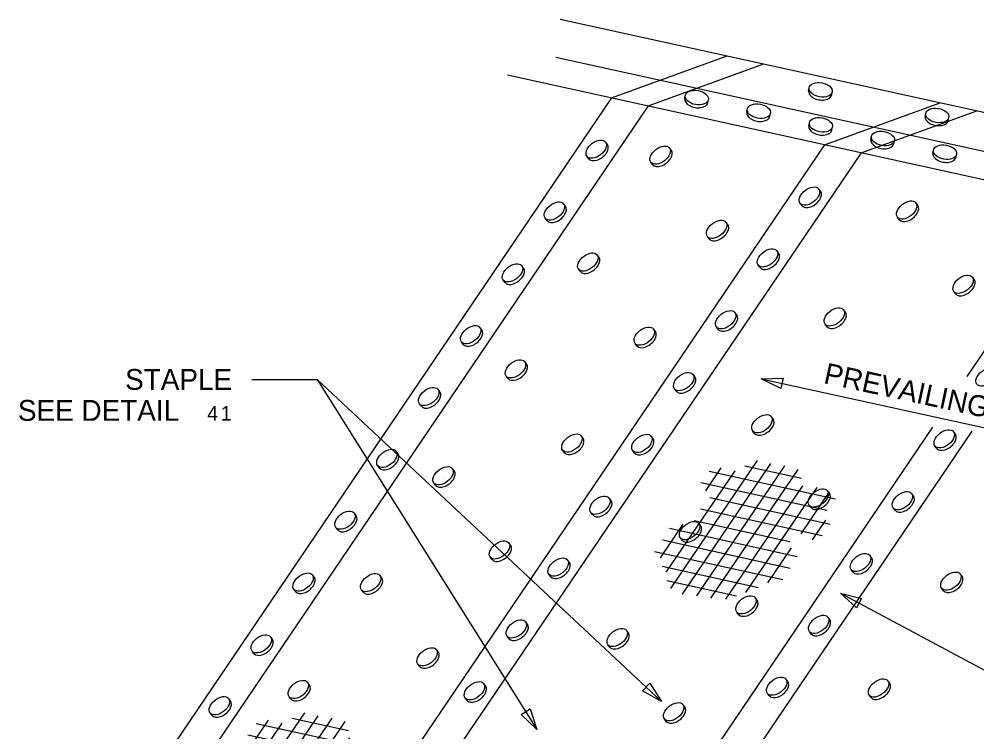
# Model space of a CAD drawing. Extents: x 27123946 to 27124151, y 1145898 to 1146027.
# Drawn here: x 27123951.53 to 27123989.43, y 1145983.24 to 1146011.45 of the extents above; entities that cross this region are included whole.
import ezdxf

# ---------------------------------------------------------------- set-up
doc = ezdxf.new("R2010")
doc.units = 0
for name, color, linetype in [('C-EROS', 7, 'Continuous'), ('C-PVMT', 7, 'Continuous'), ('Default', 7, 'Continuous'), ('G-ANNO-TEXT', 7, 'Continuous')]:
    doc.layers.add(name, color=color, linetype=linetype)

# ---------------------------------------------------------------- blocks, each defined once
blk = doc.blocks.new('mesh')
at = {"layer": 'Default'}
for p, q in [((0.00571, 0.03821), (-0.03747, -0.02556)), ((0.01235, 0.03658), (-0.03165, -0.02839)), ((0.0193, 0.03543), (-0.02443, -0.02916)), ((-0.01232, 0.03445), (-0.02009, 0.02298)), ((0.02591, 0.03375), (-0.01747, -0.03032)), ((-0.00042, 0.03553), (0.02772, 0.02934)), ((-0.00551, 0.03307), (-0.03971, -0.01743)), ((-0.01822, 0.03288), (0.04472, 0.01904)), ((-0.02236, 0.02723), (0.04043, 0.01343)), ((0.02814, 0.02562), (-0.01014, -0.03092)), ((0.03527, 0.02472), (-0.00015, -0.02758)), ((-0.0178, 0.01967), (0.04195, 0.00653)), ((0.0415, 0.0225), (0.02744, 0.00172)), ((-0.02245, 0.01413), (0.038, 0.00084)), ((-0.03125, 0.00649), (-0.0426, -0.01028)), ((-0.0256, 0.00826), (0.02188, -0.00218)), ((0.03971, 0.00843), (0.03309, -0.00136)), ((-0.03797, 0.00442), (0.0256, -0.00956)), ((-0.04137, -0.00139), (0.02214, -0.01536)), ((-0.04533, -0.00708), (0.01838, -0.02109)), ((0.02264, -0.00537), (0.01084, -0.02279)), ((-0.04159, -0.01447), (0.0063, -0.025)), ((-0.03929, -0.02154), (-0.00457, -0.02917))]:
    blk.add_line(p, q, dxfattribs=at)

msp = doc.modelspace()

# ---------------------------------------------------------------- linework, layer by layer
at = {"layer": 'C-PVMT'}
for p, q in [((27123972.944, 1146011.45), (27124008.592, 1146003.611)), ((27123972.764, 1146009.952), (27124006.832, 1146002.461)), ((27123974.969, 1146008.336), (27123979.545, 1146009.998)), ((27123976.416, 1146008.018), (27123980.992, 1146009.68)), ((27123970.86, 1146009.24), (27124004.016, 1146001.949)), ((27123982.77, 1146008.616), (27123982.791, 1146008.735)), ((27123974.969, 1146008.336), (27123954.253, 1145977.741)), ((27123977.869, 1146008.308), (27123977.89, 1146008.427)), ((27123978.326, 1146008.227), (27123978.326, 1146008.227)), ((27123978.783, 1146008.147), (27123978.804, 1146008.266)), ((27123983.227, 1146008.535), (27123983.227, 1146008.535)), ((27123983.684, 1146008.455), (27123983.705, 1146008.574)), ((27123976.416, 1146008.018), (27123955.7, 1145977.423)), ((27123980.324, 1146007.768), (27123980.345, 1146007.887)), ((27123983.404, 1146006.481), (27123987.98, 1146008.144)), ((27123984.851, 1146006.163), (27123989.427, 1146007.825)), ((27123980.781, 1146007.687), (27123980.781, 1146007.687)), ((27123981.238, 1146007.607), (27123981.259, 1146007.726)), ((27123987.383, 1146007.601), (27123987.404, 1146007.721)), ((27123987.84, 1146007.521), (27123987.84, 1146007.521)), ((27123988.297, 1146007.44), (27123988.318, 1146007.56)), ((27123982.779, 1146007.228), (27123982.8, 1146007.347)), ((27123983.236, 1146007.147), (27123983.236, 1146007.147)), ((27123983.693, 1146007.067), (27123983.714, 1146007.186)), ((27123985.234, 1146006.688), (27123985.255, 1146006.808)), ((27123983.404, 1146006.481), (27123962.688, 1145975.887)), ((27123974.806, 1146006.494), (27123974.732, 1146006.59)), ((27123977.337, 1146006.26), (27123977.262, 1146006.355)), ((27123985.691, 1146006.608), (27123985.691, 1146006.608)), ((27123986.148, 1146006.527), (27123986.169, 1146006.646)), ((27123984.851, 1146006.163), (27123964.135, 1145975.568)), ((27123974.076, 1146005.921), (27123974.001, 1146006.017)), ((27123974.441, 1146006.208), (27123974.441, 1146006.208)), ((27123976.971, 1146005.974), (27123976.971, 1146005.974)), ((27123987.689, 1146006.148), (27123987.71, 1146006.268)), ((27123988.146, 1146006.068), (27123988.146, 1146006.068)), ((27123988.603, 1146005.987), (27123988.624, 1146006.107)), ((27123976.606, 1146005.687), (27123976.531, 1146005.783)), ((27123983.241, 1146004.639), (27123983.167, 1146004.735)), ((27123973.149, 1146004.047), (27123973.075, 1146004.142)), ((27123982.511, 1146004.067), (27123982.436, 1146004.162)), ((27123982.876, 1146004.353), (27123982.876, 1146004.353)), ((27123987.091, 1146004.087), (27123987.016, 1146004.182)), ((27123993.71, 1146004.215), (27123989.032, 1145997.305)), ((27123972.784, 1146003.761), (27123972.784, 1146003.761)), ((27123986.726, 1146003.8), (27123986.726, 1146003.8)), ((27123972.419, 1146003.474), (27123972.344, 1146003.57)), ((27123979.57, 1146003.323), (27123979.495, 1146003.419)), ((27123986.36, 1146003.514), (27123986.285, 1146003.61)), ((27123979.204, 1146003.037), (27123979.204, 1146003.037)), ((27123978.839, 1146002.751), (27123978.764, 1146002.846)), ((27123981.584, 1146002.192), (27123981.51, 1146002.288)), ((27123974.473, 1146002.03), (27123974.398, 1146002.126)), ((27123981.219, 1146001.906), (27123981.219, 1146001.906)), ((27123971.492, 1146001.6), (27123971.418, 1146001.695)), ((27123973.742, 1146001.458), (27123973.667, 1146001.553)), ((27123974.107, 1146001.744), (27123974.107, 1146001.744)), ((27123980.854, 1146001.62), (27123980.779, 1146001.715)), ((27123970.762, 1146001.027), (27123970.687, 1146001.123)), ((27123971.127, 1146001.313), (27123971.127, 1146001.313)), ((27123989.324, 1146001.15), (27123989.249, 1146001.246)), ((27123988.593, 1146000.577), (27123988.518, 1146000.673)), ((27123988.959, 1146000.864), (27123988.959, 1146000.864)), ((27123984.227, 1145999.857), (27123984.152, 1145999.953)), ((27123979.927, 1145999.745), (27123979.853, 1145999.84)), ((27123983.862, 1145999.571), (27123983.862, 1145999.571)), ((27123969.835, 1145999.153), (27123969.761, 1145999.248)), ((27123976.706, 1145999.094), (27123976.631, 1145999.189)), ((27123979.197, 1145999.172), (27123979.122, 1145999.268)), ((27123979.562, 1145999.459), (27123979.562, 1145999.459)), ((27123983.496, 1145999.285), (27123983.422, 1145999.38)), ((27123969.47, 1145998.866), (27123969.47, 1145998.866)), ((27123976.34, 1145998.807), (27123976.34, 1145998.807)), ((27123969.105, 1145998.58), (27123969.03, 1145998.675)), ((27123975.975, 1145998.521), (27123975.9, 1145998.616)), ((27123971.609, 1145997.801), (27123971.534, 1145997.896)), ((27123970.878, 1145997.228), (27123970.804, 1145997.324)), ((27123971.244, 1145997.515), (27123971.244, 1145997.515)), ((27123978.27, 1145997.298), (27123978.196, 1145997.393)), ((27123977.905, 1145997.012), (27123977.905, 1145997.012)), ((27123968.178, 1145996.705), (27123968.104, 1145996.801)), ((27123977.54, 1145996.725), (27123977.465, 1145996.821)), ((27123967.448, 1145996.133), (27123967.373, 1145996.228)), ((27123967.813, 1145996.419), (27123967.813, 1145996.419)), ((27123981.363, 1145995.628), (27123981.289, 1145995.723)), ((27123980.998, 1145995.341), (27123980.998, 1145995.341)), ((27123987.672, 1145995.298), (27123972.995, 1145973.62)), ((27123973.842, 1145994.864), (27123973.767, 1145994.96)), ((27123989.23, 1145995.142), (27123974.442, 1145973.302)), ((27123976.614, 1145994.851), (27123976.539, 1145994.946)), ((27123980.633, 1145995.055), (27123980.558, 1145995.15)), ((27123988.577, 1145995.032), (27123988.502, 1145995.127)), ((27123973.477, 1145994.578), (27123973.477, 1145994.578)), ((27123976.248, 1145994.564), (27123976.248, 1145994.564)), ((27123988.211, 1145994.745), (27123988.211, 1145994.745)), ((27123966.521, 1145994.258), (27123966.447, 1145994.354)), ((27123973.111, 1145994.292), (27123973.036, 1145994.387)), ((27123975.883, 1145994.278), (27123975.808, 1145994.373)), ((27123987.846, 1145994.459), (27123987.771, 1145994.554)), ((27123966.156, 1145993.972), (27123966.156, 1145993.972)), ((27123965.791, 1145993.686), (27123965.716, 1145993.781)), ((27123968.745, 1145993.571), (27123968.67, 1145993.667)), ((27123968.014, 1145992.999), (27123967.94, 1145993.094)), ((27123968.38, 1145993.285), (27123968.38, 1145993.285)), ((27123983.596, 1145992.691), (27123983.522, 1145992.786)), ((27123986.92, 1145992.584), (27123986.845, 1145992.68)), ((27123974.957, 1145992.404), (27123974.882, 1145992.499)), ((27123983.231, 1145992.405), (27123983.231, 1145992.405)), ((27123986.554, 1145992.298), (27123986.554, 1145992.298)), ((27123964.865, 1145991.811), (27123964.79, 1145991.907)), ((27123974.226, 1145991.831), (27123974.151, 1145991.926)), ((27123974.591, 1145992.117), (27123974.591, 1145992.117)), ((27123982.866, 1145992.118), (27123982.791, 1145992.214)), ((27123986.189, 1145992.012), (27123986.114, 1145992.107)), ((27123964.499, 1145991.525), (27123964.499, 1145991.525)), ((27123964.134, 1145991.239), (27123964.059, 1145991.334)), ((27123978.5, 1145991.398), (27123978.425, 1145991.494)), ((27123977.769, 1145990.826), (27123977.694, 1145990.921)), ((27123978.134, 1145991.112), (27123978.134, 1145991.112)), ((27123970.978, 1145990.635), (27123970.903, 1145990.73)), ((27123970.247, 1145990.062), (27123970.173, 1145990.157)), ((27123970.613, 1145990.348), (27123970.613, 1145990.348)), ((27123973.3, 1145989.956), (27123973.225, 1145990.052)), ((27123985.263, 1145990.137), (27123985.188, 1145990.233)), ((27123972.934, 1145989.67), (27123972.934, 1145989.67)), ((27123984.532, 1145989.565), (27123984.457, 1145989.66)), ((27123984.897, 1145989.851), (27123984.897, 1145989.851)), ((27123963.208, 1145989.364), (27123963.133, 1145989.459)), ((27123965.881, 1145989.342), (27123965.807, 1145989.437)), ((27123972.569, 1145989.384), (27123972.494, 1145989.479)), ((27123988.842, 1145989.401), (27123988.767, 1145989.497)), ((27123962.477, 1145988.791), (27123962.402, 1145988.887)), ((27123962.842, 1145989.078), (27123962.842, 1145989.078)), ((27123965.516, 1145989.055), (27123965.516, 1145989.055)), ((27123988.111, 1145988.829), (27123988.036, 1145988.924)), ((27123988.476, 1145989.115), (27123988.476, 1145989.115)), ((27123965.151, 1145988.769), (27123965.076, 1145988.865)), ((27123980.733, 1145988.462), (27123980.658, 1145988.557)), ((27123980.367, 1145988.175), (27123980.367, 1145988.175)), ((27123980.002, 1145987.889), (27123979.927, 1145987.984)), ((27123983.606, 1145987.69), (27123983.531, 1145987.785)), ((27123971.643, 1145987.509), (27123971.568, 1145987.605)), ((27123983.24, 1145987.404), (27123983.24, 1145987.404)), ((27123961.551, 1145986.917), (27123961.476, 1145987.012)), ((27123970.912, 1145986.937), (27123970.837, 1145987.032)), ((27123971.277, 1145987.223), (27123971.277, 1145987.223)), ((27123975.636, 1145987.169), (27123975.561, 1145987.264)), ((27123982.875, 1145987.117), (27123982.8, 1145987.213)), ((27123961.185, 1145986.631), (27123961.185, 1145986.631)), ((27123974.905, 1145986.596), (27123974.83, 1145986.691)), ((27123975.27, 1145986.882), (27123975.27, 1145986.882)), ((27123960.82, 1145986.344), (27123960.745, 1145986.44)), ((27123968.114, 1145986.405), (27123968.04, 1145986.501)), ((27123967.384, 1145985.832), (27123967.309, 1145985.928)), ((27123967.749, 1145986.119), (27123967.749, 1145986.119)), ((27123963.018, 1145985.112), (27123962.943, 1145985.208)), ((27123969.986, 1145985.062), (27123969.911, 1145985.157)), ((27123981.949, 1145985.243), (27123981.874, 1145985.338)), ((27123985.978, 1145985.172), (27123985.903, 1145985.267)), ((27123962.652, 1145984.826), (27123962.652, 1145984.826)), ((27123969.62, 1145984.776), (27123969.62, 1145984.776)), ((27123981.218, 1145984.67), (27123981.143, 1145984.766)), ((27123981.583, 1145984.957), (27123981.583, 1145984.957)), ((27123985.612, 1145984.885), (27123985.612, 1145984.885)), ((27123959.894, 1145984.47), (27123959.819, 1145984.565)), ((27123962.287, 1145984.54), (27123962.212, 1145984.635)), ((27123969.255, 1145984.489), (27123969.18, 1145984.585)), ((27123977.869, 1145984.232), (27123977.794, 1145984.327)), ((27123985.247, 1145984.599), (27123985.172, 1145984.694)), ((27123959.163, 1145983.897), (27123959.088, 1145983.992)), ((27123959.528, 1145984.183), (27123959.528, 1145984.183)), ((27123977.503, 1145983.946), (27123977.503, 1145983.946)), ((27123977.138, 1145983.659), (27123977.063, 1145983.755))]:
    msp.add_line(p, q, dxfattribs=at)
for centre, major_axis in [((27123983.248, 1146008.655), (-0.457, 0.081)), ((27123978.347, 1146008.346), (-0.457, 0.081)), ((27123980.802, 1146007.807), (-0.457, 0.081)), ((27123987.861, 1146007.64), (-0.457, 0.081)), ((27123983.257, 1146007.267), (-0.457, 0.081)), ((27123974.366, 1146006.303), (-0.365, -0.286)), ((27123985.712, 1146006.727), (-0.457, 0.081)), ((27123976.896, 1146006.069), (-0.365, -0.286)), ((27123988.167, 1146006.187), (-0.457, 0.081)), ((27123982.801, 1146004.448), (-0.365, -0.286)), ((27123972.709, 1146003.856), (-0.365, -0.286)), ((27123986.651, 1146003.896), (-0.365, -0.286)), ((27123979.129, 1146003.132), (-0.365, -0.286)), ((27123974.033, 1146001.839), (-0.365, -0.286)), ((27123981.144, 1146002.001), (-0.365, -0.286)), ((27123971.052, 1146001.409), (-0.365, -0.286)), ((27123988.884, 1146000.959), (-0.365, -0.286)), ((27123979.487, 1145999.554), (-0.365, -0.286)), ((27123983.787, 1145999.666), (-0.365, -0.286)), ((27123969.395, 1145998.962), (-0.365, -0.286)), ((27123976.266, 1145998.903), (-0.365, -0.286)), ((27123971.169, 1145997.61), (-0.365, -0.286)), ((27123989.793, 1145997.288), (-0.365, -0.286)), ((27123977.83, 1145997.107), (-0.365, -0.286)), ((27123967.738, 1145996.515), (-0.365, -0.286)), ((27123980.923, 1145995.437), (-0.365, -0.286)), ((27123973.402, 1145994.673), (-0.365, -0.286)), ((27123976.173, 1145994.66), (-0.365, -0.286)), ((27123988.137, 1145994.841), (-0.365, -0.286)), ((27123966.081, 1145994.067), (-0.365, -0.286)), ((27123968.305, 1145993.38), (-0.365, -0.286)), ((27123983.156, 1145992.5), (-0.365, -0.286)), ((27123986.48, 1145992.393), (-0.365, -0.286)), ((27123974.516, 1145992.213), (-0.365, -0.286)), ((27123964.424, 1145991.62), (-0.365, -0.286)), ((27123978.059, 1145991.207), (-0.365, -0.286)), ((27123970.538, 1145990.444), (-0.365, -0.286)), ((27123972.859, 1145989.765), (-0.365, -0.286)), ((27123984.823, 1145989.946), (-0.365, -0.286)), ((27123962.767, 1145989.173), (-0.365, -0.286)), ((27123965.441, 1145989.151), (-0.365, -0.286)), ((27123988.401, 1145989.21), (-0.365, -0.286)), ((27123980.292, 1145988.271), (-0.365, -0.286)), ((27123983.166, 1145987.499), (-0.365, -0.286)), ((27123971.203, 1145987.318), (-0.365, -0.286)), ((27123975.196, 1145986.978), (-0.365, -0.286)), ((27123961.11, 1145986.726), (-0.365, -0.286)), ((27123967.674, 1145986.214), (-0.365, -0.286)), ((27123962.578, 1145984.921), (-0.365, -0.286)), ((27123969.546, 1145984.871), (-0.365, -0.286)), ((27123981.509, 1145985.052), (-0.365, -0.286)), ((27123985.538, 1145984.981), (-0.365, -0.286)), ((27123959.454, 1145984.279), (-0.365, -0.286)), ((27123977.429, 1145984.041), (-0.365, -0.286))]:
    msp.add_ellipse(centre, major_axis=major_axis, ratio=0.604498, dxfattribs=at)
for centre, major_axis in [((27123983.227, 1146008.535), (-0.457, 0.081)), ((27123978.326, 1146008.227), (-0.457, 0.081)), ((27123980.781, 1146007.687), (-0.457, 0.081)), ((27123987.84, 1146007.521), (-0.457, 0.081)), ((27123983.236, 1146007.147), (-0.457, 0.081)), ((27123985.691, 1146006.608), (-0.457, 0.081)), ((27123974.441, 1146006.208), (-0.365, -0.286)), ((27123976.971, 1146005.974), (-0.365, -0.286)), ((27123988.146, 1146006.068), (-0.457, 0.081)), ((27123982.876, 1146004.353), (-0.365, -0.286)), ((27123972.784, 1146003.761), (-0.365, -0.286)), ((27123986.726, 1146003.8), (-0.365, -0.286)), ((27123979.204, 1146003.037), (-0.365, -0.286)), ((27123981.219, 1146001.906), (-0.365, -0.286)), ((27123974.107, 1146001.744), (-0.365, -0.286)), ((27123971.127, 1146001.313), (-0.365, -0.286)), ((27123988.959, 1146000.864), (-0.365, -0.286)), ((27123979.562, 1145999.459), (-0.365, -0.286)), ((27123983.862, 1145999.571), (-0.365, -0.286)), ((27123969.47, 1145998.866), (-0.365, -0.286)), ((27123976.34, 1145998.807), (-0.365, -0.286)), ((27123971.244, 1145997.515), (-0.365, -0.286)), ((27123977.905, 1145997.012), (-0.365, -0.286)), ((27123967.813, 1145996.419), (-0.365, -0.286)), ((27123980.998, 1145995.341), (-0.365, -0.286)), ((27123988.211, 1145994.745), (-0.365, -0.286)), ((27123973.477, 1145994.578), (-0.365, -0.286)), ((27123976.248, 1145994.564), (-0.365, -0.286)), ((27123966.156, 1145993.972), (-0.365, -0.286)), ((27123968.38, 1145993.285), (-0.365, -0.286)), ((27123983.231, 1145992.405), (-0.365, -0.286)), ((27123974.591, 1145992.117), (-0.365, -0.286)), ((27123986.554, 1145992.298), (-0.365, -0.286)), ((27123964.499, 1145991.525), (-0.365, -0.286)), ((27123978.134, 1145991.112), (-0.365, -0.286)), ((27123970.613, 1145990.348), (-0.365, -0.286)), ((27123984.897, 1145989.851), (-0.365, -0.286)), ((27123972.934, 1145989.67), (-0.365, -0.286)), ((27123962.842, 1145989.078), (-0.365, -0.286)), ((27123965.516, 1145989.055), (-0.365, -0.286)), ((27123988.476, 1145989.115), (-0.365, -0.286)), ((27123980.367, 1145988.175), (-0.365, -0.286)), ((27123971.277, 1145987.223), (-0.365, -0.286)), ((27123983.24, 1145987.404), (-0.365, -0.286)), ((27123975.27, 1145986.882), (-0.365, -0.286)), ((27123961.185, 1145986.631), (-0.365, -0.286)), ((27123967.749, 1145986.119), (-0.365, -0.286)), ((27123962.652, 1145984.826), (-0.365, -0.286)), ((27123981.583, 1145984.957), (-0.365, -0.286)), ((27123985.612, 1145984.885), (-0.365, -0.286)), ((27123969.62, 1145984.776), (-0.365, -0.286)), ((27123959.528, 1145984.183), (-0.365, -0.286)), ((27123977.503, 1145983.946), (-0.365, -0.286))]:
    msp.add_ellipse(centre, major_axis=major_axis, ratio=0.604498, start_param=0, end_param=3.141593, dxfattribs=at)
at = {"layer": 'G-ANNO-TEXT'}
for p, q in [((27123980.899, 1145997.218), (27123994.22, 1145994.289)), ((27123960.732, 1145997.194), (27123963.321, 1145997.194)), ((27123963.321, 1145997.194), (27123972.017, 1145983.333)), ((27123963.321, 1145997.194), (27123976.953, 1145984.449)), ((27123984.027, 1145988.731), (27124005.37, 1145977.306))]:
    msp.add_line(p, q, dxfattribs=at)
for points in [[(27123981.668, 1145996.836), (27123980.899, 1145997.218), (27123981.758, 1145997.243)], [(27123984.664, 1145988.154), (27123984.027, 1145988.731), (27123984.86, 1145988.521)], [(27123976.487, 1145985.17), (27123976.953, 1145984.449), (27123976.202, 1145984.866)], [(27123971.751, 1145984.15), (27123972.017, 1145983.333), (27123971.398, 1145983.928)]]:
    msp.add_lwpolyline(points, close=True, dxfattribs=at)

# ---------------------------------------------------------------- block references
at = {"layer": 'C-EROS', "xscale": 79.55254830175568, "yscale": 79.55254830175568}
for p in [(27123980.283, 1145990.949), (27123962.361, 1145980.964)]:
    msp.add_blockref('mesh', p, dxfattribs=at)

# ---------------------------------------------------------------- texts
at = {"layer": 'G-ANNO-TEXT'}
for s, height, p in [('STAPLE', 0.8257, (27123955.723, 1145996.78)), ('SEE DETAIL ', 0.82569, (27123951.479, 1145995.554)), ('4', 0.578, (27123958.97, 1145995.562)), ('1', 0.578, (27123959.507, 1145995.562))]:
    msp.add_text(s, height=height, dxfattribs=at).set_placement(p)
msp.add_text('PREVAILING WIND', height=0.82569, rotation=347.9229, dxfattribs=at).set_placement((27123983.328, 1145997.05))

doc.saveas('drawing.dxf')
